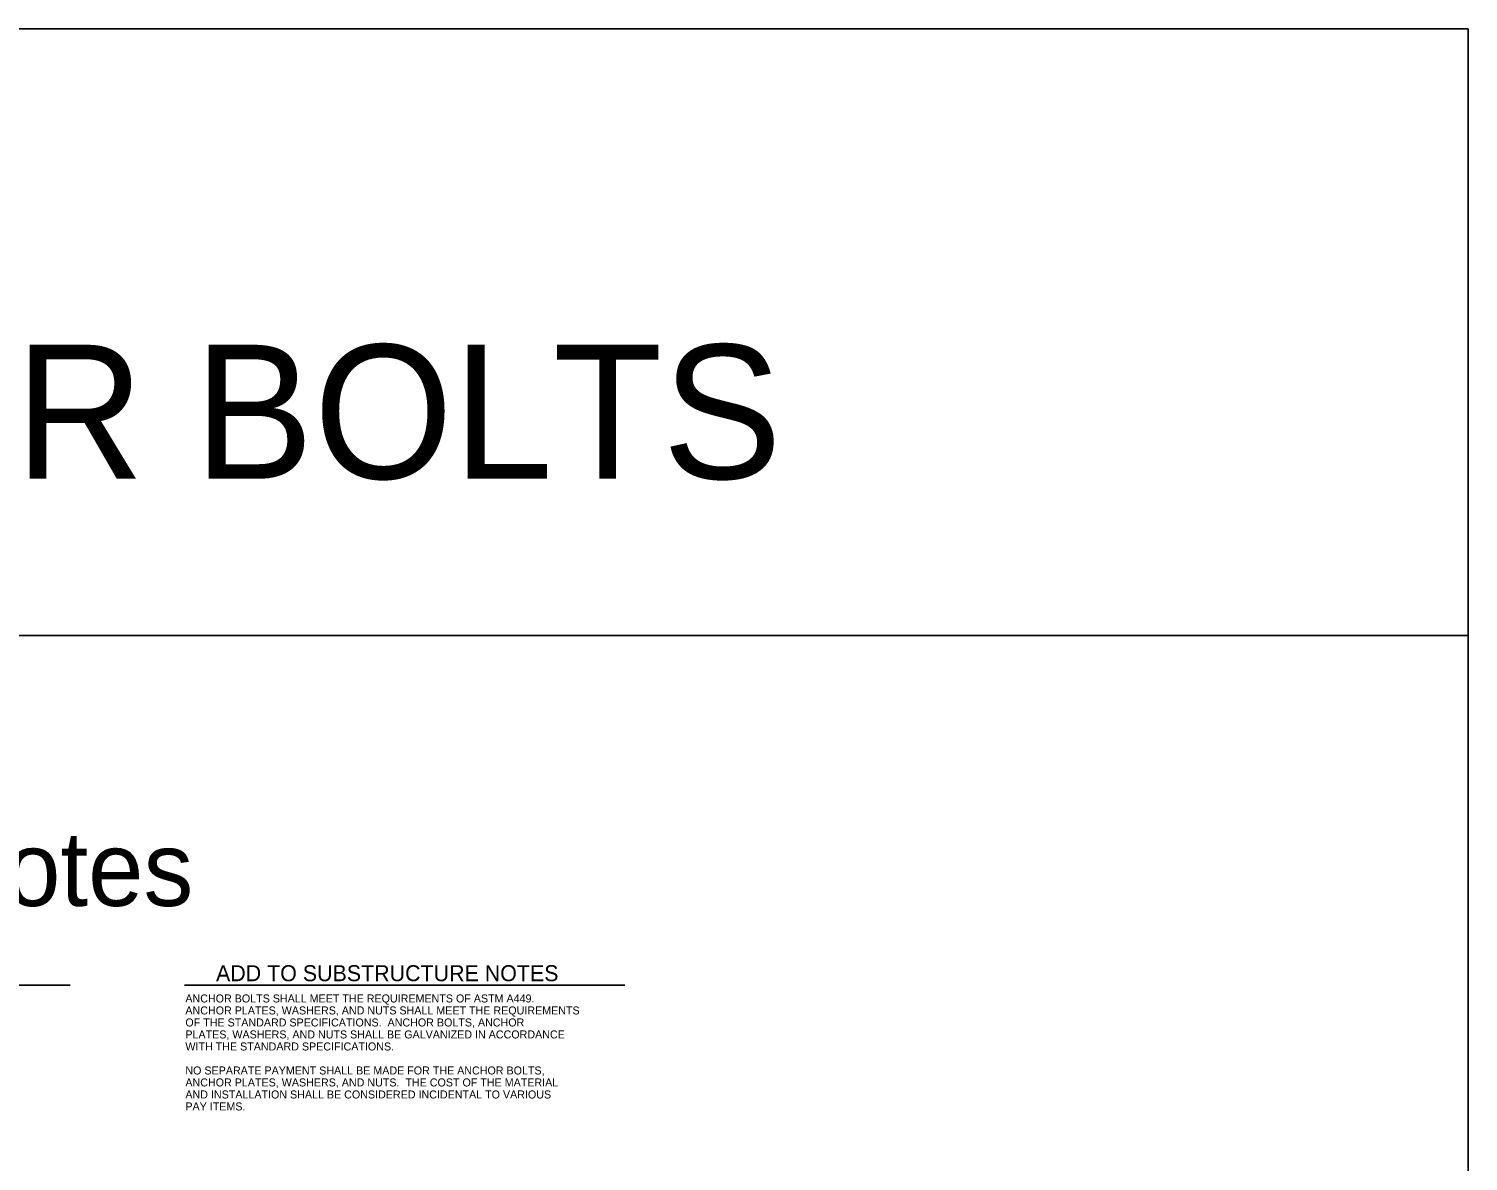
# Model space of a CAD drawing. Extents: x 0 to 177, y -1 to 127.
# Drawn here: x 53.76 to 79.48, y 77.76 to 98 of the extents above; entities that cross this region are included whole.
import ezdxf

# ---------------------------------------------------------------- set-up
doc = ezdxf.new("R2010")
doc.units = 0
for name, color, linetype in [('Plan Sheet', 7, 'Continuous'), ('Subtitle Text', 7, 'Continuous'), ('Text', 7, 'Continuous'), ('Title Text', 7, 'Continuous')]:
    doc.layers.add(name, color=color, linetype=linetype)

msp = doc.modelspace()

# ---------------------------------------------------------------- linework, layer by layer
at = {"layer": 'Plan Sheet'}
for p, q in [((0, 98), (79.481, 98)), ((79.481, 98), (79.481, 0)), ((0, 87.156), (79.481, 87.156))]:
    msp.add_line(p, q, dxfattribs=at)
at = {"layer": 'Title Text'}
for p, q in [((45.156, 80.906), (54.5, 80.906)), ((56.548, 80.906), (64.413, 80.906))]:
    msp.add_line(p, q, dxfattribs=at)

# ---------------------------------------------------------------- texts
at = {"layer": 'Subtitle Text'}
for s, p in [('ANCHOR BOLTS SHALL MEET THE REQUIREMENTS OF ASTM A449.  ', (56.561, 80.598)), ('ANCHOR PLATES, WASHERS, AND NUTS SHALL MEET THE REQUIREMENTS ', (56.561, 80.384)), ('OF THE STANDARD SPECIFICATIONS.  ANCHOR BOLTS, ANCHOR ', (56.561, 80.169)), ('PLATES, WASHERS, AND NUTS SHALL BE GALVANIZED IN ACCORDANCE ', (56.561, 79.955)), ('WITH THE STANDARD SPECIFICATIONS.', (56.561, 79.74)), ('ANCHOR PLATES, WASHERS, AND NUTS.  THE COST OF THE MATERIAL ', (56.561, 79.097)), ('NO SEPARATE PAYMENT SHALL BE MADE FOR THE ANCHOR BOLTS, ', (56.561, 79.311)), ('AND INSTALLATION SHALL BE CONSIDERED INCIDENTAL TO VARIOUS ', (56.561, 78.882)), ('PAY ITEMS.', (56.561, 78.668))]:
    msp.add_text(s, height=0.143, dxfattribs=at).set_placement(p)
at = {"layer": 'Text'}
for s, height, p in [('BLOCKOUT DETAIL FOR ANCHOR BOLTS', 2.3952, (3.684, 89.958)), ('Notes', 1.3307, (52.054, 82.323))]:
    msp.add_text(s, height=height, dxfattribs=at).set_placement(p)
at = {"layer": 'Title Text'}
msp.add_text('ADD TO SUBSTRUCTURE NOTES', height=0.286, dxfattribs=at).set_placement((57.108, 80.978))

doc.saveas('drawing.dxf')
